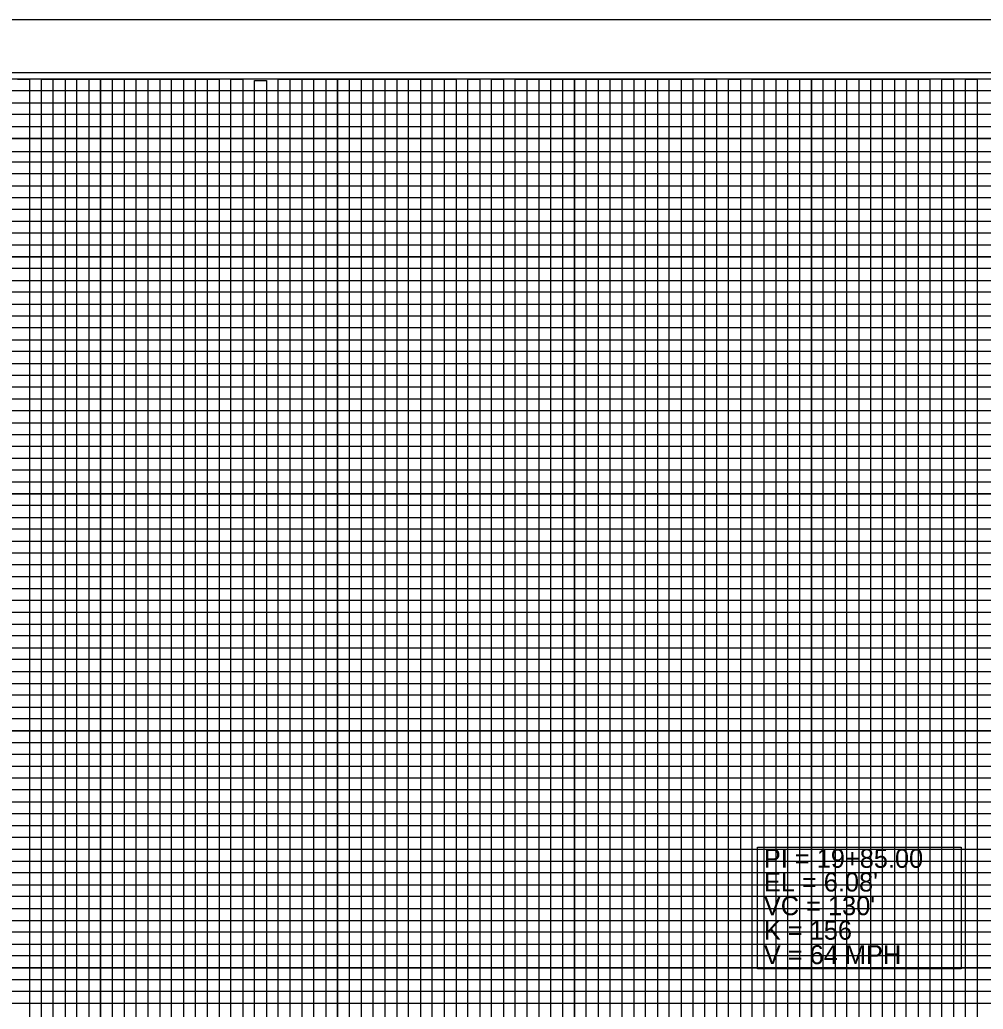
# Model space of a CAD drawing. Extents: x 575424 to 577182, y -52702 to -51602.
# Drawn here: x 576331.1 to 576737.7, y -52020 to -51602.5 of the extents above; entities that cross this region are included whole.
import ezdxf

# ---------------------------------------------------------------- set-up
doc = ezdxf.new("R2010")
doc.units = 0
for name, color, linetype in [('Prop Grid Mask', 7, 'Continuous'), ('Prop Vertical Profile Curve Label', 7, 'Continuous'), ('Prop VPI Label', 7, 'Continuous'), ('Sheet Cutting Line CELL', 7, 'Continuous'), ('Sheet DOT Grid CELL', 7, 'Continuous'), ('Sheet Layout Profile Border', 7, 'Continuous'), ('Sheet Plot Border Inside CELL', 7, 'Continuous'), ('Sheet Plot Border Outside CELL', 7, 'Continuous'), ('Sheet Profile CELL', 7, 'Continuous'), ('Sheet Profile Grid Major CELL', 7, 'Continuous'), ('Sheet Profile Grid Middle CELL', 7, 'Continuous'), ('Sheet Profile Grid Minor CELL', 7, 'Continuous')]:
    doc.layers.add(name, color=color, linetype=linetype)

msp = doc.modelspace()

# ---------------------------------------------------------------- linework, layer by layer
at = {"layer": 'Prop Grid Mask'}
msp.add_lwpolyline([(576642.52, -51951.65), (576728.34, -51951.65), (576728.34, -52003.02), (576642.52, -52003.02)], close=True, dxfattribs=at)
at = {"layer": 'Sheet Cutting Line CELL'}
msp.add_line((577182.21, -51602.49), (575498.21, -51602.49), dxfattribs=at)
at = {"layer": 'Sheet DOT Grid CELL'}
for p, q in [((576365.21, -51627.49), (576365.21, -52652.49)), ((576415.21, -51627.49), (576415.21, -52652.49)), ((576465.21, -51627.49), (576465.21, -52652.49)), ((576515.21, -51627.49), (576515.21, -52652.49)), ((576565.21, -51627.49), (576565.21, -52652.49)), ((576615.21, -51627.49), (576615.21, -52652.49)), ((576665.21, -51627.49), (576665.21, -52652.49)), ((576715.21, -51627.49), (576715.21, -52652.49)), ((575665.21, -51652.49), (576965.16, -51652.49)), ((575665.21, -51702.49), (576965.16, -51702.49)), ((575665.21, -51752.49), (576965.16, -51752.49)), ((575665.21, -51802.49), (577165.21, -51802.49)), ((575665.21, -51852.49), (577165.21, -51852.49)), ((575665.21, -51902.49), (577165.21, -51902.49)), ((575665.21, -51952.49), (577165.21, -51952.49)), ((575665.21, -52002.49), (577165.21, -52002.49))]:
    msp.add_line(p, q, dxfattribs=at)
at = {"layer": 'Sheet Layout Profile Border'}
msp.add_lwpolyline([(575715.21, -51627.49), (575715.21, -52652.49), (577115.21, -52652.49), (577115.21, -51765.04), (576965.16, -51765.04), (576965.16, -51627.49)], close=True, dxfattribs=at)
at = {"layer": 'Sheet Plot Border Inside CELL'}
msp.add_lwpolyline([(577177.71, -51624.94), (575511.21, -51624.94), (575511.21, -52680.04), (577177.71, -52680.04)], close=True, dxfattribs=at)
at = {"layer": 'Sheet Plot Border Outside CELL'}
msp.add_lwpolyline([(577182.21, -51602.49), (575498.21, -51602.49), (575498.21, -52702.49), (577182.21, -52702.49)], close=True, dxfattribs=at)
at = {"layer": 'Sheet Profile CELL'}
msp.add_lwpolyline([(577165.21, -51627.49), (575665.21, -51627.49), (575665.21, -52677.49), (577165.21, -52677.49)], close=True, dxfattribs=at)
at = {"layer": 'Sheet Profile Grid Major CELL'}
for points in [[(576365.21, -52652.49), (576365.21, -51627.49), (576415.21, -51627.49), (576415.21, -52652.49)], [(576465.21, -52652.49), (576465.21, -51627.49), (576515.21, -51627.49), (576515.21, -52652.49)], [(576565.21, -52652.49), (576565.21, -51627.49), (576615.21, -51627.49), (576615.21, -52652.49)], [(576665.21, -52652.49), (576665.21, -51627.49), (576715.21, -51627.49), (576715.21, -52652.49)], [(576965.16, -51702.49), (575665.31, -51702.49), (575665.31, -51652.54), (576965.16, -51652.54)], [(577165.21, -51802.49), (575665.21, -51802.49), (575665.21, -51752.49), (576965.16, -51752.49)], [(577165.21, -51902.49), (575665.21, -51902.49), (575665.21, -51852.49), (577165.21, -51852.49)], [(577165.21, -52002.49), (575665.21, -52002.49), (575665.21, -51952.49), (577165.21, -51952.49)]]:
    msp.add_lwpolyline(points, dxfattribs=at)
at = {"layer": 'Sheet Profile Grid Middle CELL'}
for points in [[(576340.21, -52652.49), (576340.21, -51627.49), (576390.21, -51627.49), (576390.21, -52652.49)], [(576440.21, -52652.49), (576440.21, -51627.49), (576490.21, -51627.49), (576490.21, -52652.49)], [(576540.21, -52652.49), (576540.21, -51627.49), (576590.21, -51627.49), (576590.21, -52652.49)], [(576640.21, -52652.49), (576640.21, -51627.49), (576690.21, -51627.49), (576690.21, -52652.49)], [(575665.21, -51677.49), (576965.16, -51677.49)], [(576965.16, -51727.49), (575665.21, -51727.49), (575665.21, -51777.54), (577165.21, -51777.54)], [(577165.21, -51827.49), (575665.21, -51827.49), (575665.21, -51877.49), (577165.21, -51877.49)], [(577165.21, -51927.49), (575665.21, -51927.49), (575665.21, -51977.49), (577165.21, -51977.49)]]:
    msp.add_lwpolyline(points, dxfattribs=at)
at = {"layer": 'Sheet Profile Grid Minor CELL'}
for p, q in [((577115.21, -51807.49), (575715.21, -51807.49)), ((575715.21, -51812.49), (577115.21, -51812.49)), ((577115.21, -51832.49), (575715.21, -51832.49))]:
    msp.add_line(p, q, dxfattribs=at)
for points in [[(576330.21, -51627.49), (576335.21, -51627.49), (576335.21, -52652.49)], [(576345.21, -52652.49), (576345.21, -51627.49), (576350.21, -51627.49), (576350.21, -52652.49)], [(576355.21, -52652.49), (576355.21, -51627.49), (576360.21, -51627.49), (576360.21, -52652.49)], [(576370.21, -52652.49), (576370.21, -51627.49), (576375.21, -51627.49), (576375.21, -52652.49)], [(576380.21, -52652.49), (576380.21, -51627.49), (576385.21, -51627.49), (576385.21, -52652.49)], [(576395.21, -52652.49), (576395.21, -51627.49), (576400.21, -51627.49), (576400.21, -52652.49)], [(576405.21, -52652.49), (576405.21, -51627.49), (576410.21, -51627.49), (576410.21, -52652.49)], [(576420.21, -52652.49), (576420.21, -51627.49), (576425.21, -51627.49), (576425.21, -52652.49)], [(576445.21, -52652.49), (576445.21, -51627.49), (576450.21, -51627.49), (576450.21, -52652.49)], [(576455.21, -52652.49), (576455.21, -51627.49), (576460.21, -51627.49), (576460.21, -52652.49)], [(576470.21, -52652.49), (576470.21, -51627.49), (576475.21, -51627.49), (576475.21, -52652.49)], [(576480.21, -52652.49), (576480.21, -51627.49), (576485.21, -51627.49), (576485.21, -52652.49)], [(576495.21, -52652.49), (576495.21, -51627.49), (576500.21, -51627.49), (576500.21, -52652.49)], [(576505.21, -52652.49), (576505.21, -51627.49), (576510.21, -51627.49), (576510.21, -52652.49)], [(576520.21, -52652.49), (576520.21, -51627.49), (576525.21, -51627.49), (576525.21, -52652.49)], [(576530.21, -52652.49), (576530.21, -51627.49), (576535.21, -51627.49), (576535.21, -52652.49)], [(576545.21, -52652.49), (576545.21, -51627.49), (576550.21, -51627.49), (576550.21, -52652.49)], [(576555.21, -52652.49), (576555.21, -51627.49), (576560.21, -51627.49), (576560.21, -52652.49)], [(576570.21, -52652.49), (576570.21, -51627.49), (576575.21, -51627.49), (576575.21, -52652.49)], [(576580.21, -52652.49), (576580.21, -51627.49), (576585.21, -51627.49), (576585.21, -52652.49)], [(576595.21, -52652.49), (576595.21, -51627.49), (576600.21, -51627.49), (576600.21, -52652.49)], [(576605.21, -52652.49), (576605.21, -51627.49), (576610.21, -51627.49), (576610.21, -52652.49)], [(576620.21, -52652.49), (576620.21, -51627.49), (576625.21, -51627.49), (576625.21, -52652.49)], [(576630.21, -52652.49), (576630.21, -51627.49), (576635.21, -51627.49), (576635.21, -52652.49)], [(576645.21, -52652.49), (576645.21, -51627.49), (576650.21, -51627.49), (576650.21, -52652.49)], [(576655.21, -52652.49), (576655.21, -51627.49), (576660.21, -51627.49), (576660.21, -52652.49)], [(576670.21, -52652.49), (576670.21, -51627.49), (576675.21, -51627.49), (576675.21, -52652.49)], [(576680.21, -52652.49), (576680.21, -51627.49), (576685.21, -51627.49), (576685.21, -52652.49)], [(576695.21, -52652.49), (576695.21, -51627.49), (576700.21, -51627.49), (576700.21, -52652.49)], [(576705.21, -52652.49), (576705.21, -51627.49), (576710.21, -51627.49), (576710.21, -52652.49)], [(576720.21, -52652.49), (576720.21, -51627.49), (576725.21, -51627.49), (576725.21, -52652.49)], [(576730.21, -52652.49), (576730.21, -51627.49), (576735.21, -51627.49), (576735.21, -52652.49)], [(576430.21, -52652.49), (576430.21, -51628.09), (576435.21, -51628.09), (576435.21, -52652.49)], [(576965.16, -51632.49), (575715.21, -51632.49), (575715.21, -51637.49), (576965.16, -51637.49)], [(576965.16, -51642.49), (575715.21, -51642.49), (575715.21, -51647.49), (576965.16, -51647.49)], [(576965.16, -51658.24), (575716.21, -51658.24), (575716.21, -51662.49), (576965.16, -51662.49)], [(576965.16, -51667.49), (575715.21, -51667.49), (575715.21, -51672.49), (576965.16, -51672.49)], [(576965.16, -51682.49), (575715.21, -51682.49), (575715.21, -51687.49), (576965.16, -51687.49)], [(576965.16, -51692.49), (575715.21, -51692.49), (575715.21, -51697.49), (576965.16, -51697.49)], [(576965.16, -51707.49), (575715.21, -51707.49), (575715.21, -51712.49), (576965.16, -51712.49)], [(576965.16, -51717.49), (575715.21, -51717.49), (575715.21, -51722.49), (576965.16, -51722.49)], [(576965.16, -51732.49), (575715.21, -51732.49), (575715.21, -51737.49), (576965.16, -51737.49)], [(576965.16, -51742.49), (575715.21, -51742.49), (575715.21, -51747.49), (576965.16, -51747.49)], [(576965.16, -51757.49), (575715.21, -51757.49), (575715.21, -51762.49), (576965.16, -51762.49)], [(577115.21, -51767.49), (575715.21, -51767.49), (575715.21, -51767.49), (575715.21, -51787.49), (577115.21, -51787.49)], [(575715.21, -51772.49), (577115.21, -51772.49)], [(577115.21, -51782.49), (575715.21, -51782.49)], [(577115.21, -51792.49), (575715.21, -51792.49), (575715.21, -51797.49), (577115.21, -51797.49)], [(577115.21, -51817.49), (575715.21, -51817.49), (575715.21, -51822.49), (577115.21, -51822.49)], [(577115.21, -51837.49), (575715.21, -51837.49), (575715.21, -51842.49), (577115.21, -51842.49)], [(577115.21, -51847.49), (575715.21, -51847.49)], [(575715.21, -51857.49), (577115.21, -51857.49)], [(577115.21, -51862.49), (575715.21, -51862.49), (575715.21, -51867.49), (577115.21, -51867.49)], [(577115.21, -51872.49), (575715.21, -51872.49), (575715.21, -51882.49), (577115.21, -51882.49)], [(577115.21, -51887.49), (575715.21, -51887.49), (575715.21, -51892.49), (577115.21, -51892.49)], [(577115.21, -51897.49), (575715.21, -51897.49), (575715.21, -51907.49), (577115.21, -51907.49)], [(577115.21, -51912.49), (575715.21, -51912.49), (575715.21, -51917.49), (577115.21, -51917.49)], [(577115.21, -51922.49), (575715.21, -51922.49), (575715.21, -51932.49), (577115.21, -51932.49)], [(577115.21, -51937.49), (575715.21, -51937.49), (575715.21, -51942.49), (577115.21, -51942.49)], [(577115.21, -51947.49), (575715.21, -51947.49), (575715.21, -51957.49), (577115.21, -51957.49)], [(577115.21, -51962.49), (575715.21, -51962.49), (575715.21, -51967.49), (577115.21, -51967.49)], [(577115.21, -51972.49), (575715.21, -51972.49), (575715.21, -51982.49), (577115.21, -51982.49)], [(577115.21, -51987.49), (575715.21, -51987.49), (575715.21, -51992.49), (577115.21, -51992.49)], [(577115.21, -51997.49), (575715.21, -51997.49), (575715.21, -52007.49), (577115.21, -52007.49)], [(577115.21, -52012.49), (575715.21, -52012.49), (575715.21, -52017.49), (577115.21, -52017.49)]]:
    msp.add_lwpolyline(points, dxfattribs=at)

# ---------------------------------------------------------------- texts
at = {"layer": 'Prop Vertical Profile Curve Label'}
for s, p in [("VC = 130'", (576645.15, -51980.32)), ('K = 156', (576645.15, -51990.66)), ('V = 64 MPH', (576645.15, -52000.97))]:
    msp.add_text(s, height=8, dxfattribs=at).set_placement(p)
at = {"layer": 'Prop VPI Label'}
for s, p in [('PI = 19+85.00', (576645.15, -51960.32)), ("EL = 6.08'", (576645.15, -51970.32))]:
    msp.add_text(s, height=8, dxfattribs=at).set_placement(p)

doc.saveas('drawing.dxf')
